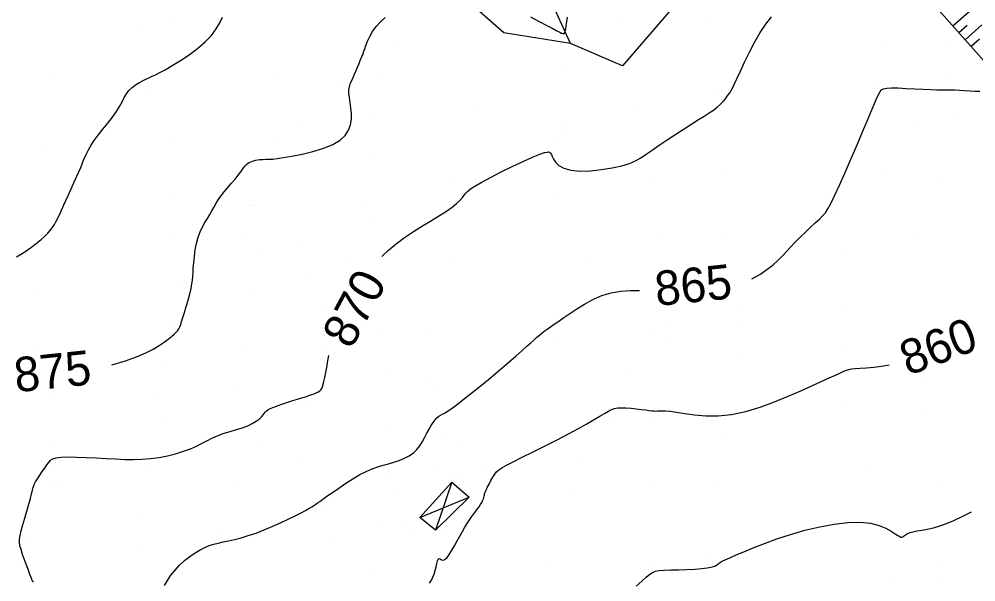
# Model space of a CAD drawing. Extents: x 400243 to 403697, y 4403637 to 4408083.
# Drawn here: x 402712.4 to 402920.2, y 4406214.4 to 4406336.6 of the extents above; entities that cross this region are included whole.
import ezdxf

# ---------------------------------------------------------------- set-up
doc = ezdxf.new("R2010")
doc.units = 0
doc.layers.add('HH_IC', color=7, linetype='Continuous')

msp = doc.modelspace()

# ---------------------------------------------------------------- linework, layer by layer
at = {"layer": 'HH_IC'}
for p, q in [((402832.11, 4406331.32), (402812.62, 4406373.9)), ((402870.61, 4406358.24), (402843.42, 4406326.49)), ((402817.62, 4406333.67), (402790.33, 4406357.62)), ((402933.83, 4406314.03), (402899.67, 4406352.63)), ((402915.15, 4406335.14), (402918.7, 4406338.28)), ((402746.36, 4406335.9), (402746.36, 4406335.9)), ((402842.79, 4406336.06), (402842.79, 4406336.06)), ((402862.61, 4406336.6), (402862.61, 4406336.6)), ((402917.8, 4406332.14), (402921.45, 4406335.38)), ((402739.08, 4406335.05), (402739.08, 4406335.05)), ((402817.62, 4406333.67), (402817.62, 4406333.67)), ((402832.11, 4406331.32), (402817.62, 4406333.67)), ((402918.28, 4406335.24), (402916.47, 4406333.64)), ((402793.94, 4406331.38), (402793.94, 4406331.38)), ((402832.11, 4406331.32), (402832.11, 4406331.32)), ((402843.42, 4406326.49), (402832.11, 4406331.32)), ((402920.98, 4406332.29), (402919.13, 4406330.65)), ((402900.43, 4406331.04), (402900.43, 4406331.04)), ((402913.75, 4406330.42), (402913.75, 4406330.42)), ((402787.17, 4406328.86), (402787.17, 4406328.86)), ((402831.09, 4406325.65), (402831.09, 4406325.65)), ((402843.42, 4406326.49), (402843.42, 4406326.49)), ((402719.21, 4406324.78), (402719.21, 4406324.78)), ((402767.65, 4406324.31), (402767.65, 4406324.31)), ((402782.02, 4406322.94), (402782.02, 4406322.94)), ((402791.23, 4406323.86), (402791.23, 4406323.86)), ((402899.21, 4406322.94), (402899.21, 4406322.94)), ((402914.34, 4406324.76), (402914.34, 4406324.76)), ((402740.99, 4406320.34), (402740.99, 4406320.34)), ((402864.18, 4406320.6), (402864.18, 4406320.6)), ((402811.07, 4406316.84), (402811.07, 4406316.84)), ((402846.27, 4406316.83), (402846.27, 4406316.83)), ((402789, 4406315.32), (402789, 4406315.32)), ((402916.15, 4406316.09), (402916.15, 4406316.09)), ((402773.52, 4406313.1), (402773.52, 4406313.1)), ((402830.68, 4406314.39), (402830.68, 4406314.39)), ((402906.72, 4406314.12), (402906.72, 4406314.12)), ((402744.84, 4406310.54), (402744.84, 4406310.54)), ((402828.83, 4406310.6), (402828.83, 4406310.6)), ((402830.45, 4406311.44), (402830.45, 4406311.44)), ((402718.41, 4406309.11), (402718.41, 4406309.11)), ((402768.01, 4406310.32), (402768.01, 4406310.32)), ((402788.28, 4406306.28), (402788.28, 4406306.28)), ((402827.66, 4406307.46), (402827.66, 4406307.46)), ((402766.05, 4406304.67), (402766.05, 4406304.67)), ((402849.82, 4406302.5), (402849.82, 4406302.5)), ((402865.3, 4406303.06), (402865.3, 4406303.06)), ((402900.12, 4406302.58), (402900.12, 4406302.58)), ((402911.71, 4406302.48), (402911.71, 4406302.48)), ((402806.18, 4406301.16), (402806.18, 4406301.16)), ((402745.98, 4406298.96), (402745.98, 4406298.96)), ((402810.02, 4406298.22), (402810.02, 4406298.22)), ((402763.14, 4406297.14), (402763.14, 4406297.14)), ((402763.38, 4406296.21), (402763.38, 4406296.21)), ((402787.77, 4406296.16), (402787.77, 4406296.16)), ((402829.73, 4406297.92), (402829.73, 4406297.92)), ((402890.24, 4406294.72), (402890.24, 4406294.72)), ((402717.38, 4406291.74), (402717.38, 4406291.74)), ((402788.28, 4406292.98), (402788.28, 4406292.98)), ((402745.28, 4406290.04), (402745.28, 4406290.04)), ((402761.95, 4406289.64), (402761.95, 4406289.64)), ((402851.49, 4406289.99), (402851.49, 4406289.99)), ((402865.4, 4406289.09), (402865.4, 4406289.09)), ((402906.79, 4406288.98), (402906.79, 4406288.98)), ((402774.21, 4406287.26), (402774.21, 4406287.26)), ((402892.1, 4406286.7), (402892.1, 4406286.7)), ((402764.93, 4406285.26), (402764.93, 4406285.26)), ((402784.1, 4406285.02), (402784.1, 4406285.02)), ((402807.22, 4406283.93), (402807.22, 4406283.93)), ((402835.76, 4406283.71), (402835.76, 4406283.71)), ((402774.28, 4406281.57), (402774.28, 4406281.57)), ((402747.05, 4406279.57), (402747.05, 4406279.57)), ((402783.18, 4406280.69), (402783.18, 4406280.69)), ((402853.07, 4406280.59), (402853.07, 4406280.59)), ((402866.16, 4406281.26), (402866.16, 4406281.26)), ((402762.56, 4406277.35), (402762.56, 4406277.35)), ((402787.52, 4406278.47), (402787.52, 4406278.47)), ((402854.02, 4406277.91), (402854.02, 4406277.91)), ((402716.4, 4406277.01), (402716.4, 4406277.01)), ((402779.27, 4406273.06), (402779.27, 4406273.06)), ((402869.54, 4406274.34), (402869.54, 4406274.34)), ((402891.47, 4406273.66), (402891.47, 4406273.66)), ((402745.26, 4406269.62), (402745.26, 4406269.62)), ((402801.67, 4406269.43), (402801.67, 4406269.43)), ((402849.3, 4406269.19), (402849.3, 4406269.19)), ((402853.05, 4406270.62), (402853.05, 4406270.62)), ((402869.2, 4406269.92), (402869.2, 4406269.92)), ((402791.2, 4406268.42), (402791.2, 4406268.42)), ((402829.13, 4406267.03), (402829.13, 4406267.03)), ((402852.87, 4406267.29), (402852.87, 4406267.29)), ((402910.17, 4406268.06), (402910.17, 4406268.06)), ((402760.72, 4406265.84), (402760.72, 4406265.84)), ((402892.19, 4406265.32), (402892.19, 4406265.32)), ((402715.97, 4406264.42), (402715.97, 4406264.42)), ((402778.2, 4406264.35), (402778.2, 4406264.35)), ((402868.86, 4406263.38), (402868.86, 4406263.38)), ((402743.39, 4406261.72), (402743.39, 4406261.72)), ((402892.06, 4406260.8), (402892.06, 4406260.8)), ((402791.62, 4406259.77), (402791.62, 4406259.77)), ((402844.81, 4406259.44), (402844.81, 4406259.44)), ((402759.14, 4406256.38), (402759.14, 4406256.38)), ((402776.81, 4406256.55), (402776.81, 4406256.55)), ((402800.95, 4406257.46), (402800.95, 4406257.46)), ((402908.83, 4406257.82), (402908.83, 4406257.82)), ((402718.84, 4406254.36), (402718.84, 4406254.36)), ((402802.36, 4406255.67), (402802.36, 4406255.67)), ((402742.44, 4406253.92), (402742.44, 4406253.92)), ((402775.67, 4406252.91), (402775.67, 4406252.91)), ((402892.34, 4406252.4), (402892.34, 4406252.4)), ((402766.31, 4406250.64), (402766.31, 4406250.64)), ((402841.44, 4406250.23), (402841.44, 4406250.23)), ((402909.4, 4406251.95), (402909.4, 4406251.95)), ((402743.22, 4406249.08), (402743.22, 4406249.08)), ((402850.55, 4406249.61), (402850.55, 4406249.61)), ((402792.28, 4406248.04), (402792.28, 4406248.04)), ((402803.83, 4406246.56), (402803.83, 4406246.56)), ((402719, 4406243.91), (402719, 4406243.91)), ((402764.38, 4406244.46), (402764.38, 4406244.46)), ((402865.87, 4406245.8), (402865.87, 4406245.8)), ((402808.54, 4406243.53), (402808.54, 4406243.53)), ((402772.64, 4406241.15), (402772.64, 4406241.15)), ((402834.53, 4406240.17), (402834.53, 4406240.17)), ((402740.39, 4406239.31), (402740.39, 4406239.31)), ((402802.26, 4406238.27), (402802.26, 4406238.27)), ((402812.66, 4406239.18), (402812.66, 4406239.18)), ((402896.71, 4406238.5), (402896.71, 4406238.5)), ((402792.56, 4406237.48), (402792.56, 4406237.48)), ((402799.37, 4406228.37), (402806.35, 4406236.07)), ((402806.35, 4406236.07), (402802.77, 4406225.62)), ((402805.84, 4406236.64), (402805.84, 4406236.64)), ((402806.35, 4406236.07), (402806.35, 4406236.07)), ((402806.35, 4406236.07), (402810.12, 4406232.76)), ((402808.79, 4406236.71), (402808.79, 4406236.71)), ((402718.72, 4406234.98), (402718.72, 4406234.98)), ((402721.14, 4406235.58), (402721.14, 4406235.58)), ((402760.15, 4406235.02), (402760.15, 4406235.02)), ((402793.66, 4406233.71), (402793.66, 4406233.71)), ((402810.25, 4406233.54), (402810.25, 4406233.54)), ((402832.58, 4406234.25), (402832.58, 4406234.25)), ((402849.77, 4406234.94), (402849.77, 4406234.94)), ((402864.21, 4406235.09), (402864.21, 4406235.09)), ((402911.61, 4406235.24), (402911.61, 4406235.24)), ((402799.37, 4406228.37), (402810.12, 4406232.76)), ((402801.95, 4406232.62), (402801.95, 4406232.62)), ((402810.12, 4406232.76), (402802.77, 4406225.62)), ((402810.12, 4406232.76), (402810.12, 4406232.76)), ((402778.74, 4406230.67), (402778.74, 4406230.67)), ((402738.66, 4406228.8), (402738.66, 4406228.8)), ((402799.37, 4406228.37), (402799.37, 4406228.37)), ((402802.77, 4406225.62), (402799.37, 4406228.37)), ((402799.4, 4406227.87), (402799.4, 4406227.87)), ((402809.09, 4406229.04), (402809.09, 4406229.04)), ((402790.22, 4406226.49), (402790.22, 4406226.49)), ((402795.33, 4406226.63), (402795.33, 4406226.63)), ((402797.44, 4406225.86), (402797.44, 4406225.86)), ((402802.77, 4406225.62), (402802.77, 4406225.62)), ((402804.67, 4406225.24), (402804.67, 4406225.24)), ((402714.79, 4406223.24), (402714.79, 4406223.24)), ((402756.5, 4406224.73), (402756.5, 4406224.73)), ((402779.98, 4406223.72), (402779.98, 4406223.72)), ((402802.69, 4406224.44), (402802.69, 4406224.44)), ((402904.35, 4406225.12), (402904.35, 4406225.12)), ((402904.73, 4406223.99), (402904.73, 4406223.99)), ((402756.08, 4406222.37), (402756.08, 4406222.37)), ((402738.99, 4406220.94), (402738.99, 4406220.94)), ((402862.24, 4406220.22), (402862.24, 4406220.22)), ((402827.51, 4406217.79), (402827.51, 4406217.79)), ((402849.67, 4406218), (402849.67, 4406218)), ((402912.62, 4406217.42), (402912.62, 4406217.42)), ((402789.3, 4406215.7), (402789.3, 4406215.7)), ((402901.6, 4406215.32), (402901.6, 4406215.32)), ((402715.51, 4406214.67), (402715.51, 4406214.67)), ((402912.72, 4406214.78), (402912.72, 4406214.78))]:
    msp.add_line(p, q, dxfattribs=at)
for points in [[(402711.78, 4406284.97), (402713.35, 4406285.94), (402714.81, 4406286.92), (402716.08, 4406287.87), (402717.12, 4406288.73), (402717.94, 4406289.49), (402718.57, 4406290.16), (402719.06, 4406290.72), (402719.43, 4406291.19), (402719.72, 4406291.59), (402720, 4406292), (402720.31, 4406292.57), (402720.73, 4406293.4), (402721.31, 4406294.62), (402722.08, 4406296.29), (402722.99, 4406298.3), (402723.96, 4406300.44), (402724.9, 4406302.55), (402725.72, 4406304.43), (402726.37, 4406305.96), (402726.9, 4406307.2), (402727.41, 4406308.25), (402727.97, 4406309.24), (402728.66, 4406310.28), (402729.54, 4406311.44), (402730.55, 4406312.71), (402731.61, 4406314.02), (402732.62, 4406315.32), (402733.5, 4406316.56), (402734.18, 4406317.68), (402734.72, 4406318.69), (402735.19, 4406319.6), (402735.66, 4406320.41), (402736.21, 4406321.14), (402736.88, 4406321.8), (402737.65, 4406322.38), (402738.47, 4406322.88), (402739.27, 4406323.31), (402740.01, 4406323.66), (402740.66, 4406323.95), (402741.28, 4406324.22), (402741.99, 4406324.55), (402742.89, 4406325), (402744.08, 4406325.64), (402745.62, 4406326.53), (402747.41, 4406327.62), (402749.3, 4406328.88), (402751.13, 4406330.24), (402752.77, 4406331.66), (402754.11, 4406333.09), (402755.15, 4406334.49), (402755.95, 4406335.83), (402756.56, 4406337.07)], [(402732.52, 4406261.54), (402735.43, 4406262.38), (402737.88, 4406263.25), (402739.87, 4406264.12), (402741.49, 4406264.96), (402742.8, 4406265.76), (402743.86, 4406266.48), (402744.73, 4406267.13), (402745.44, 4406267.69), (402746.01, 4406268.18), (402746.46, 4406268.62), (402746.8, 4406269.02), (402747.05, 4406269.39), (402747.26, 4406269.79), (402747.45, 4406270.29), (402747.65, 4406270.94), (402747.92, 4406271.81), (402748.26, 4406272.92), (402748.64, 4406274.22), (402749.04, 4406275.59), (402749.41, 4406276.92), (402749.7, 4406278.12), (402749.9, 4406279.11), (402750.02, 4406279.95), (402750.08, 4406280.74), (402750.13, 4406281.58), (402750.18, 4406282.55), (402750.27, 4406283.74), (402750.41, 4406285.08), (402750.6, 4406286.49), (402750.87, 4406287.91), (402751.23, 4406289.25), (402751.67, 4406290.44), (402752.17, 4406291.51), (402752.7, 4406292.46), (402753.24, 4406293.34), (402753.74, 4406294.16), (402754.19, 4406294.96), (402754.62, 4406295.74), (402755.07, 4406296.52), (402755.58, 4406297.34), (402756.18, 4406298.19), (402756.89, 4406299.1), (402757.69, 4406300.04), (402758.5, 4406300.97), (402759.28, 4406301.87), (402759.96, 4406302.71), (402760.5, 4406303.46), (402760.95, 4406304.1), (402761.37, 4406304.66), (402761.82, 4406305.12), (402762.35, 4406305.49), (402763.02, 4406305.76), (402763.78, 4406305.96), (402764.55, 4406306.1), (402765.29, 4406306.17), (402765.92, 4406306.2), (402766.41, 4406306.21), (402766.88, 4406306.21), (402767.48, 4406306.24), (402768.37, 4406306.34), (402769.71, 4406306.54), (402771.57, 4406306.86), (402773.8, 4406307.3), (402776.18, 4406307.87), (402778.5, 4406308.57), (402780.51, 4406309.38), (402782.07, 4406310.32), (402783.18, 4406311.36), (402783.91, 4406312.47), (402784.33, 4406313.66), (402784.52, 4406314.88), (402784.53, 4406316.12), (402784.43, 4406317.35), (402784.27, 4406318.52), (402784.11, 4406319.59), (402784, 4406320.52), (402784, 4406321.28), (402784.09, 4406321.92), (402784.26, 4406322.5), (402784.5, 4406323.09), (402784.8, 4406323.75), (402785.14, 4406324.51), (402785.5, 4406325.35), (402785.85, 4406326.19), (402786.18, 4406326.97), (402786.46, 4406327.63), (402786.67, 4406328.13), (402786.81, 4406328.47), (402786.91, 4406328.7), (402786.97, 4406328.84), (402787.01, 4406328.94), (402787.03, 4406329.01), (402787.06, 4406329.12), (402787.12, 4406329.32), (402787.23, 4406329.65), (402787.41, 4406330.17), (402787.67, 4406330.91), (402788.04, 4406331.82), (402788.52, 4406332.85), (402789.14, 4406333.94), (402789.91, 4406335.03), (402790.82, 4406336.06), (402791.83, 4406337)], [(402791.12, 4406285.1), (402792.61, 4406286.42), (402794.27, 4406287.81), (402796.09, 4406289.18), (402798.02, 4406290.5), (402799.99, 4406291.73), (402801.89, 4406292.88), (402803.66, 4406293.94), (402805.19, 4406294.91), (402806.41, 4406295.78), (402807.37, 4406296.56), (402808.09, 4406297.25), (402808.63, 4406297.85), (402809.04, 4406298.36), (402809.38, 4406298.8), (402809.78, 4406299.24), (402810.37, 4406299.73), (402811.31, 4406300.35), (402812.73, 4406301.17), (402814.72, 4406302.22), (402817.08, 4406303.42), (402819.58, 4406304.65), (402821.96, 4406305.78), (402823.98, 4406306.69), (402825.46, 4406307.3), (402826.44, 4406307.63), (402827.04, 4406307.76), (402827.36, 4406307.77), (402827.53, 4406307.73), (402827.64, 4406307.68), (402827.73, 4406307.61), (402827.82, 4406307.47), (402827.95, 4406307.22), (402828.14, 4406306.81), (402828.42, 4406306.22), (402828.87, 4406305.53), (402829.59, 4406304.83), (402830.66, 4406304.22), (402832.15, 4406303.79), (402834.13, 4406303.62), (402836.42, 4406303.68), (402838.84, 4406303.93), (402841.19, 4406304.3), (402843.25, 4406304.76), (402844.9, 4406305.26), (402846.23, 4406305.83), (402847.39, 4406306.48), (402848.54, 4406307.26), (402849.84, 4406308.18), (402851.39, 4406309.25), (402853.14, 4406310.43), (402854.97, 4406311.64), (402856.77, 4406312.82), (402858.45, 4406313.89), (402859.92, 4406314.8), (402861.17, 4406315.57), (402862.25, 4406316.25), (402863.17, 4406316.88), (402863.96, 4406317.49), (402864.65, 4406318.11), (402865.24, 4406318.74), (402865.74, 4406319.33), (402866.16, 4406319.87), (402866.49, 4406320.33), (402866.76, 4406320.71), (402867.01, 4406321.11), (402867.3, 4406321.65), (402867.69, 4406322.45), (402868.24, 4406323.64), (402869, 4406325.29), (402869.93, 4406327.29), (402870.99, 4406329.48), (402872.14, 4406331.68), (402873.34, 4406333.74), (402874.55, 4406335.54), (402875.75, 4406337.14)], [(402823.39, 4406337.13), (402825.34, 4406336.14), (402826.99, 4406335.27), (402828.25, 4406334.6), (402829.15, 4406334.11), (402829.76, 4406333.78), (402830.16, 4406333.58), (402830.43, 4406333.48), (402830.62, 4406333.45), (402830.76, 4406333.52), (402830.88, 4406333.7), (402830.98, 4406334.03), (402831.07, 4406334.53), (402831.19, 4406335.21), (402831.32, 4406336.05), (402831.47, 4406337.02)], [(402871.48, 4406280.18), (402873.23, 4406281.16), (402874.78, 4406282.21), (402876.13, 4406283.26), (402877.24, 4406284.25), (402878.19, 4406285.2), (402879.06, 4406286.14), (402879.92, 4406287.1), (402880.85, 4406288.1), (402881.91, 4406289.18), (402883.05, 4406290.28), (402884.19, 4406291.36), (402885.25, 4406292.35), (402886.16, 4406293.19), (402886.88, 4406293.88), (402887.47, 4406294.56), (402888.03, 4406295.39), (402888.66, 4406296.56), (402889.47, 4406298.25), (402890.52, 4406300.56), (402891.74, 4406303.34), (402893.05, 4406306.35), (402894.34, 4406309.35), (402895.53, 4406312.12), (402896.52, 4406314.47), (402897.34, 4406316.4), (402897.99, 4406317.95), (402898.52, 4406319.17), (402898.93, 4406320.09), (402899.27, 4406320.76), (402899.62, 4406321.23), (402900.1, 4406321.51), (402900.81, 4406321.66), (402901.86, 4406321.7), (402903.3, 4406321.67), (402905.02, 4406321.59), (402906.88, 4406321.5), (402908.7, 4406321.4), (402910.35, 4406321.32), (402911.7, 4406321.28), (402912.8, 4406321.26), (402913.75, 4406321.26), (402914.64, 4406321.26), (402915.56, 4406321.24), (402916.58, 4406321.2), (402917.67, 4406321.14), (402918.81, 4406321.08), (402919.94, 4406321.01), (402921.03, 4406320.94)], [(402743.95, 4406213.63), (402744.59, 4406214.71), (402745.33, 4406215.84), (402746.21, 4406216.96), (402747.21, 4406218.03), (402748.3, 4406219.03), (402749.43, 4406219.94), (402750.57, 4406220.73), (402751.66, 4406221.38), (402752.68, 4406221.89), (402753.65, 4406222.28), (402754.61, 4406222.58), (402755.6, 4406222.83), (402756.67, 4406223.07), (402757.85, 4406223.32), (402759.16, 4406223.62), (402760.58, 4406223.98), (402762.13, 4406224.44), (402763.81, 4406225.01), (402765.61, 4406225.7), (402767.45, 4406226.48), (402769.26, 4406227.29), (402770.94, 4406228.08), (402772.42, 4406228.8), (402773.62, 4406229.42), (402774.57, 4406229.93), (402775.31, 4406230.35), (402775.9, 4406230.7), (402776.37, 4406230.99), (402776.78, 4406231.26), (402777.19, 4406231.54), (402777.68, 4406231.88), (402778.34, 4406232.34), (402779.22, 4406232.98), (402780.39, 4406233.81), (402781.77, 4406234.78), (402783.28, 4406235.81), (402784.84, 4406236.81), (402786.35, 4406237.69), (402787.74, 4406238.39), (402789.03, 4406238.93), (402790.25, 4406239.36), (402791.42, 4406239.73), (402792.58, 4406240.06), (402793.76, 4406240.4), (402794.92, 4406240.79), (402796.03, 4406241.23), (402797.06, 4406241.75), (402797.98, 4406242.39), (402798.75, 4406243.14), (402799.41, 4406243.98), (402799.97, 4406244.88), (402800.47, 4406245.8), (402800.93, 4406246.71), (402801.39, 4406247.56), (402801.83, 4406248.34), (402802.27, 4406249.03), (402802.69, 4406249.61), (402803.09, 4406250.05), (402803.5, 4406250.36), (402804, 4406250.65), (402804.71, 4406251.06), (402805.73, 4406251.7), (402807.18, 4406252.72), (402809.12, 4406254.2), (402811.41, 4406256.02), (402813.84, 4406258.01), (402816.23, 4406260), (402818.39, 4406261.83), (402820.16, 4406263.35), (402821.56, 4406264.58), (402822.66, 4406265.56), (402823.53, 4406266.35), (402824.23, 4406266.99), (402824.83, 4406267.52), (402825.36, 4406267.98), (402825.88, 4406268.4), (402826.42, 4406268.82), (402827.02, 4406269.27), (402827.73, 4406269.78), (402828.57, 4406270.37), (402829.55, 4406271.05), (402830.68, 4406271.83), (402832, 4406272.71), (402833.5, 4406273.71), (402835.17, 4406274.74), (402836.98, 4406275.72), (402838.92, 4406276.57), (402840.96, 4406277.21), (402843.05, 4406277.57), (402845.13, 4406277.7), (402847.11, 4406277.71)], [(402715.44, 4406214.33), (402715.35, 4406214.45), (402715.29, 4406214.54), (402715.24, 4406214.61), (402715.19, 4406214.73), (402715.1, 4406214.96), (402714.94, 4406215.36), (402714.7, 4406216), (402714.36, 4406216.91), (402713.95, 4406218.01), (402713.52, 4406219.2), (402713.11, 4406220.37), (402712.77, 4406221.42), (402712.54, 4406222.26), (402712.43, 4406222.99), (402712.44, 4406223.7), (402712.56, 4406224.5), (402712.8, 4406225.51), (402713.16, 4406226.79), (402713.59, 4406228.26), (402714.04, 4406229.79), (402714.46, 4406231.26), (402714.82, 4406232.53), (402715.07, 4406233.53), (402715.25, 4406234.3), (402715.42, 4406234.93), (402715.62, 4406235.51), (402715.92, 4406236.11), (402716.34, 4406236.81), (402716.85, 4406237.58), (402717.39, 4406238.36), (402717.93, 4406239.12), (402718.4, 4406239.8), (402718.78, 4406240.36), (402719.16, 4406240.8), (402719.66, 4406241.13), (402720.39, 4406241.36), (402721.47, 4406241.49), (402722.97, 4406241.53), (402724.82, 4406241.5), (402726.9, 4406241.42), (402729.08, 4406241.32), (402731.26, 4406241.2), (402733.32, 4406241.09), (402735.29, 4406241.01), (402737.18, 4406240.99), (402739.04, 4406241.04), (402740.89, 4406241.19), (402742.74, 4406241.44), (402744.58, 4406241.8), (402746.35, 4406242.24), (402748.02, 4406242.75), (402749.54, 4406243.31), (402750.88, 4406243.9), (402752.09, 4406244.51), (402753.24, 4406245.1), (402754.38, 4406245.68), (402755.57, 4406246.2), (402756.87, 4406246.66), (402758.22, 4406247.07), (402759.57, 4406247.47), (402760.85, 4406247.87), (402762.01, 4406248.3), (402763, 4406248.77), (402763.81, 4406249.27), (402764.46, 4406249.77), (402764.97, 4406250.24), (402765.34, 4406250.65), (402765.6, 4406250.99), (402765.82, 4406251.26), (402766.06, 4406251.51), (402766.4, 4406251.75), (402766.91, 4406252.02), (402767.65, 4406252.34), (402768.58, 4406252.69), (402769.62, 4406253.05), (402770.71, 4406253.42), (402771.79, 4406253.76), (402772.8, 4406254.08), (402773.72, 4406254.36), (402774.55, 4406254.62), (402775.28, 4406254.85), (402775.91, 4406255.06), (402776.44, 4406255.26), (402776.87, 4406255.45), (402777.22, 4406255.63), (402777.5, 4406255.8), (402777.73, 4406255.98), (402777.93, 4406256.17), (402778.1, 4406256.41), (402778.25, 4406256.75), (402778.41, 4406257.23), (402778.57, 4406257.91), (402778.76, 4406258.81), (402778.95, 4406259.84), (402779.15, 4406260.93), (402779.33, 4406261.97), (402779.48, 4406262.87), (402779.6, 4406263.56)], [(402801.48, 4406214.1), (402801.91, 4406214.74), (402802.24, 4406215.39), (402802.51, 4406216.1), (402802.73, 4406216.88), (402802.91, 4406217.68), (402803.07, 4406218.41), (402803.22, 4406218.99), (402803.39, 4406219.35), (402803.6, 4406219.44), (402803.84, 4406219.35), (402804.12, 4406219.2), (402804.46, 4406219.13), (402804.85, 4406219.27), (402805.31, 4406219.7), (402805.82, 4406220.39), (402806.37, 4406221.27), (402806.94, 4406222.26), (402807.51, 4406223.3), (402808.08, 4406224.33), (402808.64, 4406225.31), (402809.18, 4406226.25), (402809.7, 4406227.11), (402810.2, 4406227.89), (402810.68, 4406228.58), (402811.13, 4406229.18), (402811.55, 4406229.73), (402811.93, 4406230.23), (402812.27, 4406230.71), (402812.57, 4406231.17), (402812.82, 4406231.61), (402813.02, 4406232.03), (402813.18, 4406232.4), (402813.29, 4406232.72), (402813.35, 4406232.98), (402813.4, 4406233.23), (402813.46, 4406233.51), (402813.57, 4406233.85), (402813.76, 4406234.32), (402814.04, 4406234.93), (402814.41, 4406235.65), (402814.82, 4406236.4), (402815.24, 4406237.12), (402815.65, 4406237.76), (402816.04, 4406238.28), (402816.51, 4406238.72), (402817.18, 4406239.19), (402818.19, 4406239.75), (402819.65, 4406240.5), (402821.64, 4406241.49), (402824.02, 4406242.66), (402826.62, 4406243.95), (402829.24, 4406245.27), (402831.71, 4406246.54), (402833.86, 4406247.7), (402835.69, 4406248.73), (402837.23, 4406249.63), (402838.5, 4406250.39), (402839.53, 4406251), (402840.35, 4406251.48), (402841.03, 4406251.83), (402841.68, 4406252.06), (402842.36, 4406252.19), (402843.16, 4406252.23), (402844.15, 4406252.2), (402845.26, 4406252.11), (402846.4, 4406251.98), (402847.49, 4406251.85), (402848.44, 4406251.73), (402849.18, 4406251.63), (402849.75, 4406251.56), (402850.21, 4406251.52), (402850.6, 4406251.5), (402850.99, 4406251.51), (402851.44, 4406251.54), (402852, 4406251.55), (402852.76, 4406251.53), (402853.79, 4406251.45), (402855.16, 4406251.27), (402856.92, 4406250.99), (402859.05, 4406250.69), (402861.49, 4406250.48), (402864.19, 4406250.46), (402867.11, 4406250.75), (402870.19, 4406251.41), (402873.33, 4406252.37), (402876.43, 4406253.51), (402879.39, 4406254.73), (402882.11, 4406255.92), (402884.51, 4406256.98), (402886.56, 4406257.9), (402888.28, 4406258.68), (402889.67, 4406259.31), (402890.73, 4406259.8), (402891.5, 4406260.16), (402892.07, 4406260.4), (402892.58, 4406260.55), (402893.17, 4406260.66), (402893.96, 4406260.73), (402895.06, 4406260.81), (402896.41, 4406260.92), (402897.96, 4406261.06), (402899.63, 4406261.27), (402901.34, 4406261.57)], [(402846.4, 4406213.48), (402847.57, 4406214.55), (402848.55, 4406215.42), (402849.31, 4406216.04), (402849.94, 4406216.45), (402850.57, 4406216.7), (402851.36, 4406216.84), (402852.43, 4406216.91), (402853.87, 4406216.98), (402855.57, 4406217.04), (402857.37, 4406217.11), (402859.1, 4406217.19), (402860.61, 4406217.3), (402861.76, 4406217.42), (402862.59, 4406217.57), (402863.17, 4406217.73), (402863.58, 4406217.9), (402863.86, 4406218.07), (402864.1, 4406218.24), (402864.31, 4406218.4), (402864.5, 4406218.55), (402864.69, 4406218.69), (402864.9, 4406218.83), (402865.14, 4406218.96), (402865.49, 4406219.12), (402866.05, 4406219.36), (402866.89, 4406219.72), (402868.11, 4406220.24), (402869.76, 4406220.95), (402871.81, 4406221.81), (402874.22, 4406222.76), (402876.94, 4406223.75), (402879.9, 4406224.72), (402883.04, 4406225.61), (402886.25, 4406226.38), (402889.41, 4406226.96), (402892.38, 4406227.31), (402895.04, 4406227.37), (402897.29, 4406227.12), (402899.14, 4406226.64), (402900.63, 4406226.03), (402901.78, 4406225.4), (402902.64, 4406224.85), (402903.24, 4406224.47), (402903.63, 4406224.25), (402903.87, 4406224.14), (402904.01, 4406224.12), (402904.1, 4406224.13), (402904.19, 4406224.16), (402904.3, 4406224.21), (402904.41, 4406224.27), (402904.54, 4406224.35), (402904.68, 4406224.46), (402904.85, 4406224.6), (402905.07, 4406224.76), (402905.39, 4406224.93), (402905.85, 4406225.11), (402906.5, 4406225.29), (402907.36, 4406225.45), (402908.41, 4406225.63), (402909.61, 4406225.86), (402910.92, 4406226.15), (402912.32, 4406226.55), (402913.78, 4406227.08), (402915.37, 4406227.76), (402917.15, 4406228.59), (402919.21, 4406229.59)]]:
    msp.add_lwpolyline(points, dxfattribs=at)

# ---------------------------------------------------------------- texts
for s, rotation, p in [('870', 61.8631, (402784.47, 4406264.71)), ('865', 5.7923, (402850.81, 4406274.31)), ('860', 20.7074, (402905.44, 4406259.11)), ('875', 6.0383, (402711.67, 4406255.56))]:
    msp.add_text(s, height=7.5, rotation=rotation, dxfattribs=at).set_placement(p)

doc.saveas('drawing.dxf')
